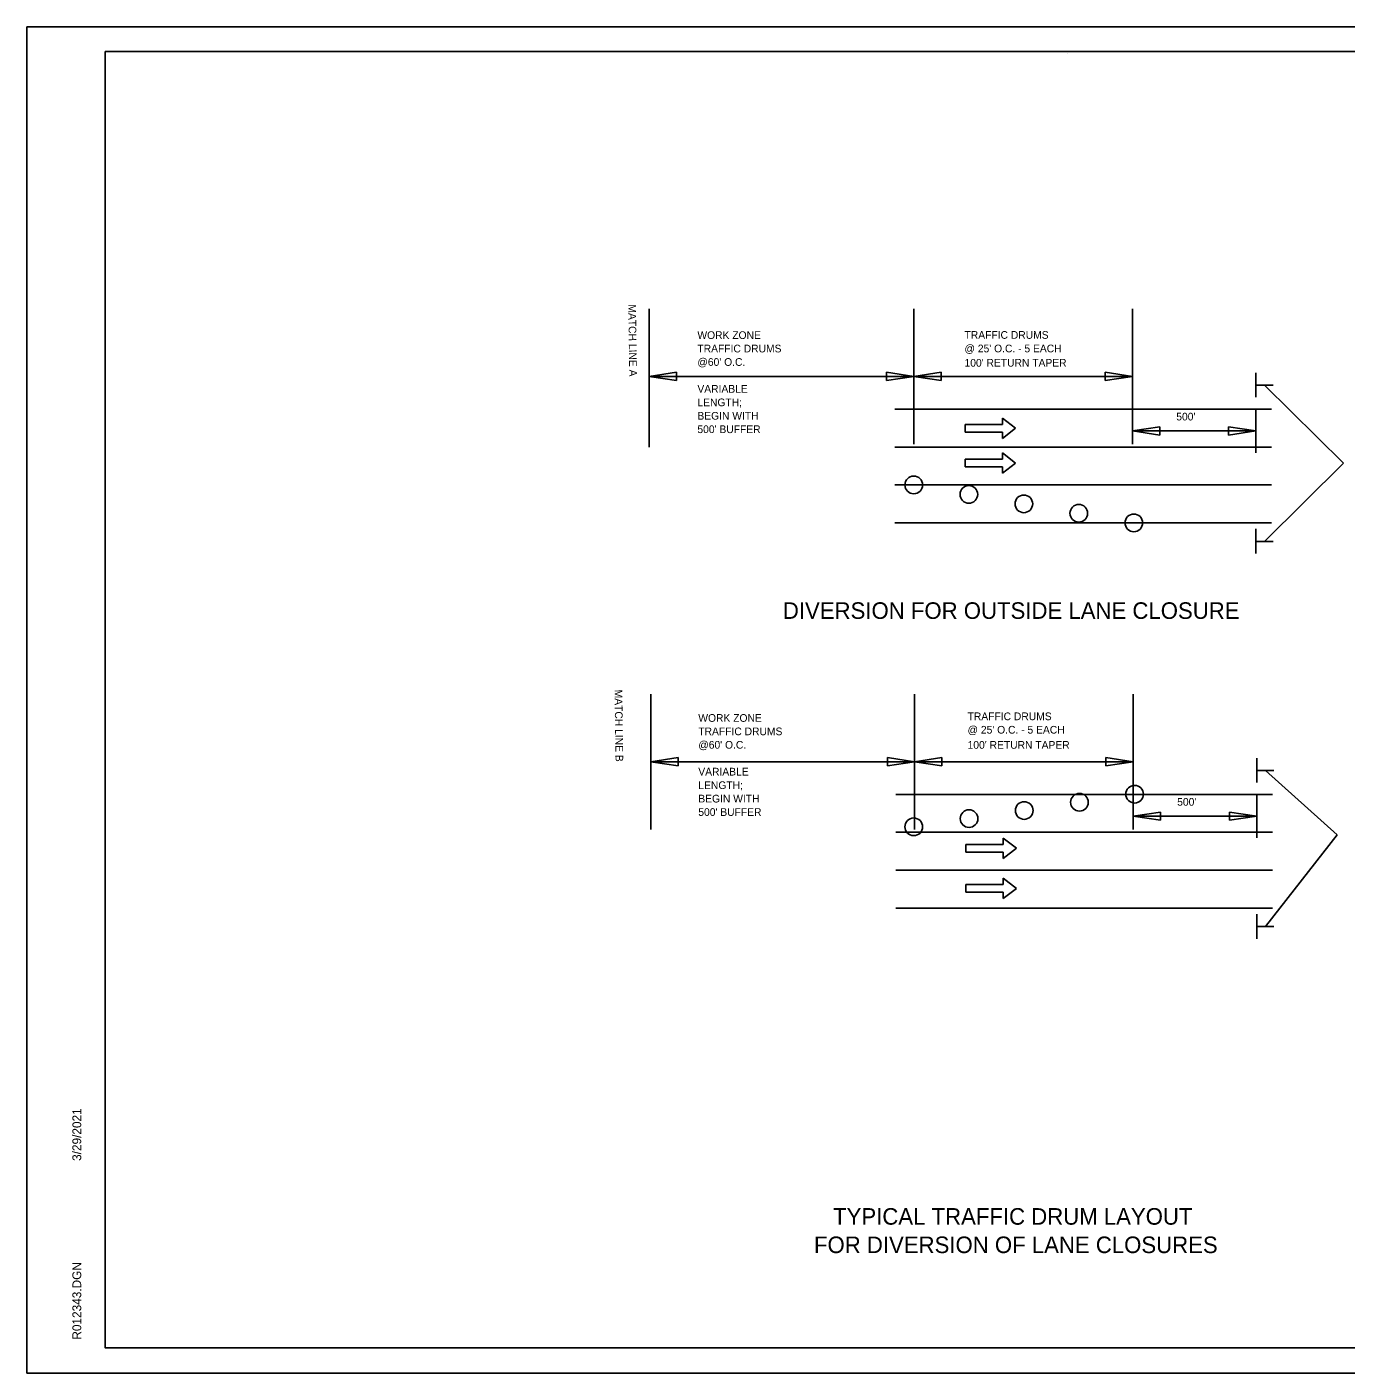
# Model space of a CAD drawing. Extents: x 1397271 to 1411271, y 376395 to 377888.
# Drawn here: x 1406605 to 1408068, y 376395 to 377888 of the extents above; entities that cross this region are included whole.
import ezdxf

# ---------------------------------------------------------------- set-up
doc = ezdxf.new("R2010")
doc.units = 0
for name, color, linetype in [('Default', 7, 'Continuous'), ('R_Border', 7, 'Continuous'), ('R_Border Notes', 7, 'Continuous'), ('R_Draft', 7, 'Continuous'), ('R_MOT', 7, 'Continuous'), ('R_No Plot', 7, 'Continuous')]:
    doc.layers.add(name, color=color, linetype=linetype)

msp = doc.modelspace()

# ---------------------------------------------------------------- linework, layer by layer
at = {"layer": 'Default'}
for p, q in [((1407294.9, 377575.3), (1407294.9, 377421.9)), ((1407588.4, 377575.3), (1407588.4, 377425.2)), ((1407830.8, 377575.3), (1407830.8, 377425.2)), ((1407294.9, 377500.2), (1407325.2, 377504.8)), ((1407588.4, 377500.2), (1407294.9, 377500.2)), ((1407325.2, 377495.7), (1407294.9, 377500.2)), ((1407325.2, 377504.8), (1407325.2, 377495.7)), ((1407558.1, 377495.7), (1407558.1, 377504.8)), ((1407558.1, 377504.8), (1407588.4, 377500.2)), ((1407588.4, 377500.2), (1407558.1, 377495.7)), ((1407588.4, 377500.2), (1407618.7, 377504.8)), ((1407588.4, 377500.2), (1407618.7, 377504.8)), ((1407830.8, 377500.2), (1407588.4, 377500.2)), ((1407618.7, 377495.7), (1407588.4, 377500.2)), ((1407618.7, 377495.7), (1407588.4, 377500.2)), ((1407618.7, 377504.8), (1407618.7, 377495.7)), ((1407618.7, 377504.8), (1407618.7, 377495.7)), ((1407800.5, 377495.7), (1407800.5, 377504.8)), ((1407800.5, 377504.8), (1407830.8, 377500.2)), ((1407830.8, 377500.2), (1407800.5, 377495.7)), ((1407567.4, 377464), (1407985.3, 377464)), ((1407967.7, 377464), (1407967.7, 377415.6)), ((1407686.6, 377447), (1407645.3, 377447)), ((1407645.3, 377447), (1407645.3, 377438.6)), ((1407686.6, 377454), (1407686.6, 377447)), ((1407686.6, 377454), (1407701.2, 377442.8)), ((1407701.2, 377442.8), (1407686.6, 377431.5)), ((1407830.8, 377439.8), (1407861.1, 377444.3)), ((1407861.1, 377435.2), (1407830.8, 377439.8)), ((1407861.1, 377444.3), (1407861.1, 377435.2)), ((1407937.4, 377435.2), (1407937.4, 377444.3)), ((1407937.4, 377444.3), (1407967.7, 377439.8)), ((1407967.7, 377439.8), (1407937.4, 377435.2)), ((1407686.6, 377438.6), (1407645.3, 377438.6)), ((1407686.6, 377438.6), (1407686.6, 377431.5)), ((1407567.4, 377421.9), (1407985.3, 377421.9)), ((1407686.6, 377415.5), (1407686.6, 377408.4)), ((1407686.6, 377415.5), (1407701.2, 377404.2)), ((1407686.6, 377408.4), (1407645.3, 377408.4)), ((1407645.3, 377408.4), (1407645.3, 377400)), ((1407686.6, 377400), (1407645.3, 377400)), ((1407701.2, 377404.2), (1407686.6, 377393)), ((1407686.6, 377400), (1407686.6, 377393)), ((1407567.4, 377379.9), (1407985.3, 377379.9)), ((1407567.4, 377337.9), (1407985.3, 377337.9)), ((1407296.8, 377147.9), (1407296.8, 376997.8)), ((1407589.3, 377147.9), (1407589.3, 376997.8)), ((1407831.7, 377147.9), (1407831.7, 376997.8)), ((1407296.8, 377072.8), (1407327.1, 377077.4)), ((1407589.3, 377072.8), (1407296.8, 377072.8)), ((1407327.1, 377068.3), (1407296.8, 377072.8)), ((1407327.1, 377077.4), (1407327.1, 377068.3)), ((1407559, 377068.3), (1407559, 377077.4)), ((1407559, 377077.4), (1407589.3, 377072.8)), ((1407589.3, 377072.8), (1407559, 377068.3)), ((1407589.3, 377072.8), (1407619.6, 377077.4)), ((1407589.3, 377072.8), (1407619.6, 377077.4)), ((1407831.7, 377072.8), (1407589.3, 377072.8)), ((1407619.6, 377068.3), (1407589.3, 377072.8)), ((1407619.6, 377068.3), (1407589.3, 377072.8)), ((1407619.6, 377077.4), (1407619.6, 377068.3)), ((1407619.6, 377077.4), (1407619.6, 377068.3)), ((1407801.4, 377068.3), (1407801.4, 377077.4)), ((1407801.4, 377077.4), (1407831.7, 377072.8)), ((1407831.7, 377072.8), (1407801.4, 377068.3)), ((1407568.3, 377036.6), (1407986.2, 377036.6)), ((1407968.7, 377036.6), (1407968.7, 376988.2)), ((1407831.7, 377012.4), (1407862, 377016.9)), ((1407862, 377007.8), (1407831.7, 377012.4)), ((1407862, 377016.9), (1407862, 377007.8)), ((1407938.4, 377007.8), (1407938.4, 377016.9)), ((1407938.4, 377016.9), (1407968.7, 377012.4)), ((1407968.7, 377012.4), (1407938.4, 377007.8)), ((1407568.3, 376994.5), (1407986.2, 376994.5)), ((1407687.5, 376981), (1407646.2, 376981)), ((1407646.2, 376981), (1407646.2, 376972.6)), ((1407687.5, 376988.1), (1407687.5, 376981)), ((1407687.5, 376988.1), (1407702.1, 376976.8)), ((1407702.1, 376976.8), (1407687.5, 376965.6)), ((1407687.5, 376972.6), (1407646.2, 376972.6)), ((1407687.5, 376972.6), (1407687.5, 376965.6)), ((1407568.3, 376952.5), (1407986.2, 376952.5)), ((1407687.5, 376936.6), (1407646.2, 376936.6)), ((1407646.2, 376936.6), (1407646.2, 376928.1)), ((1407687.5, 376943.6), (1407687.5, 376936.6)), ((1407687.5, 376943.6), (1407702.1, 376932.3)), ((1407702.1, 376932.3), (1407687.5, 376921.1)), ((1407687.5, 376928.1), (1407646.2, 376928.1)), ((1407687.5, 376928.1), (1407687.5, 376921.1)), ((1407568.3, 376910.5), (1407986.2, 376910.5))]:
    msp.add_line(p, q, dxfattribs=at)
at = {"layer": 'R_Border'}
for p, q in [((1406691.4, 377860.7), (1408904.7, 377860.7)), ((1406691.4, 376422.5), (1406691.4, 377860.7)), ((1407759.1, 377858.9), (1407759.1, 377858.9)), ((1407759.1, 377858.9), (1407759.1, 377858.9)), ((1406691.4, 376422.5), (1406691.4, 376422.5)), ((1408904.7, 376422.5), (1406691.4, 376422.5))]:
    msp.add_line(p, q, dxfattribs=at)
at = {"layer": 'R_Border Notes'}
for p, q in [((1407967.7, 377439.8), (1407830.8, 377439.8)), ((1407968.7, 377012.4), (1407831.7, 377012.4))]:
    msp.add_line(p, q, dxfattribs=at)
at = {"layer": 'R_Draft'}
for p, q in [((1407977.5, 377490.6), (1408065.1, 377403.9)), ((1408065.1, 377403.9), (1407977.5, 377317.3)), ((1408057.8, 376991.7), (1407978.4, 377063.2)), ((1408057.8, 376991.7), (1407978.4, 376889.9))]:
    msp.add_line(p, q, dxfattribs=at)
at = {"layer": 'R_MOT'}
for p, q in [((1407967.7, 377477.1), (1407967.7, 377504.3)), ((1407968.1, 377490.6), (1407986.8, 377490.6)), ((1407967.7, 377303.8), (1407967.7, 377331.1)), ((1407968.1, 377317.3), (1407986.8, 377317.3)), ((1407968.7, 377049.7), (1407968.7, 377076.9)), ((1407969.1, 377063.2), (1407987.7, 377063.2)), ((1407968.7, 376876.4), (1407968.7, 376903.7)), ((1407969.1, 376889.9), (1407987.7, 376889.9))]:
    msp.add_line(p, q, dxfattribs=at)
for centre in [(1407588.3, 377379.9), (1407649.4, 377369.4), (1407710.4, 377358.9), (1407771.4, 377348.4), (1407832.4, 377337.8), (1407772.1, 377027.8), (1407833.3, 377036.8), (1407710.8, 377018.7), (1407588.3, 377000.6), (1407649.6, 377009.7)]:
    msp.add_circle(centre, 9.8, dxfattribs=at)
at = {"layer": 'R_No Plot'}
for p, q in [((1406604.6, 377888), (1408938, 377888)), ((1406604.6, 376394.6), (1408938, 376394.6))]:
    msp.add_line(p, q, dxfattribs=at)
for points in [[(1406604.6, 377888), (1408938, 377888), (1408938, 376394.6), (1406604.6, 376394.6)], [(1408328.9, 377860.7), (1408328.9, 377791.6), (1408579, 377791.6), (1408579, 377771.1), (1408741.4, 377771.1), (1408741.4, 377600.8), (1408904.7, 377600.8), (1408904.7, 376422.5), (1406691.4, 376422.5), (1406691.4, 377860.7)]]:
    msp.add_lwpolyline(points, close=True, dxfattribs=at)

# ---------------------------------------------------------------- texts
at = {"layer": 'Default'}
for s, p in [('MATCH LINE A', (1407271.6, 377580.1)), ('MATCH LINE B', (1407256.4, 377152.7))]:
    msp.add_text(s, height=8.54, rotation=270.8059, dxfattribs=at).set_placement(p)
for s, height, p in [('WORK ZONE', 8.54, (1407348.3, 377541.8)), ('TRAFFIC DRUMS', 8.54, (1407644.6, 377542)), ('TRAFFIC DRUMS ', 8.54, (1407348.3, 377526.9)), ("@ 25' O.C. - 5 EACH", 8.54, (1407644.6, 377527)), ("@60' O.C.", 8.54, (1407348.3, 377512)), ("100' RETURN TAPER", 8.54, (1407644.6, 377511.1)), ('VARIABLE', 8.54, (1407348.3, 377482.2)), ('LENGTH;', 8.54, (1407348.3, 377467.2)), ('BEGIN WITH', 8.54, (1407348.3, 377452.3)), ("500'", 8.54, (1407879.5, 377451.4)), ("500' BUFFER", 8.54, (1407348.3, 377437.4)), ('DIVERSION FOR OUTSIDE LANE CLOSURE', 18.375, (1407443.1, 377231.3)), ('TRAFFIC DRUMS', 8.54, (1407648, 377118.9)), ('WORK ZONE', 8.54, (1407349.3, 377117.1)), ("@ 25' O.C. - 5 EACH", 8.54, (1407648, 377104)), ('TRAFFIC DRUMS ', 8.54, (1407349.3, 377102.2)), ("@60' O.C.", 8.54, (1407349.3, 377087.3)), ("100' RETURN TAPER", 8.54, (1407648, 377087.2)), ('VARIABLE', 8.54, (1407349.3, 377057.5)), ('LENGTH;', 8.54, (1407349.3, 377042.5)), ('BEGIN WITH', 8.54, (1407349.3, 377027.6)), ("500'", 8.54, (1407880.5, 377024)), ("500' BUFFER", 8.54, (1407349.3, 377012.7))]:
    msp.add_text(s, height=height, dxfattribs=at).set_placement(p)
at = {"layer": 'R_Border'}
for s, p in [('3/29/2021', (1406664.8, 376630)), ('R012343.DGN', (1406664.8, 376431.7))]:
    msp.add_text(s, height=9.8, rotation=90, dxfattribs=at).set_placement(p)
at = {"layer": 'R_Border Notes'}
for s, p in [('TYPICAL TRAFFIC DRUM LAYOUT', (1407498.8, 376559.2)), ('FOR DIVERSION OF LANE CLOSURES', (1407477.6, 376527.7))]:
    msp.add_text(s, height=18.375, dxfattribs=at).set_placement(p)

doc.saveas('drawing.dxf')
